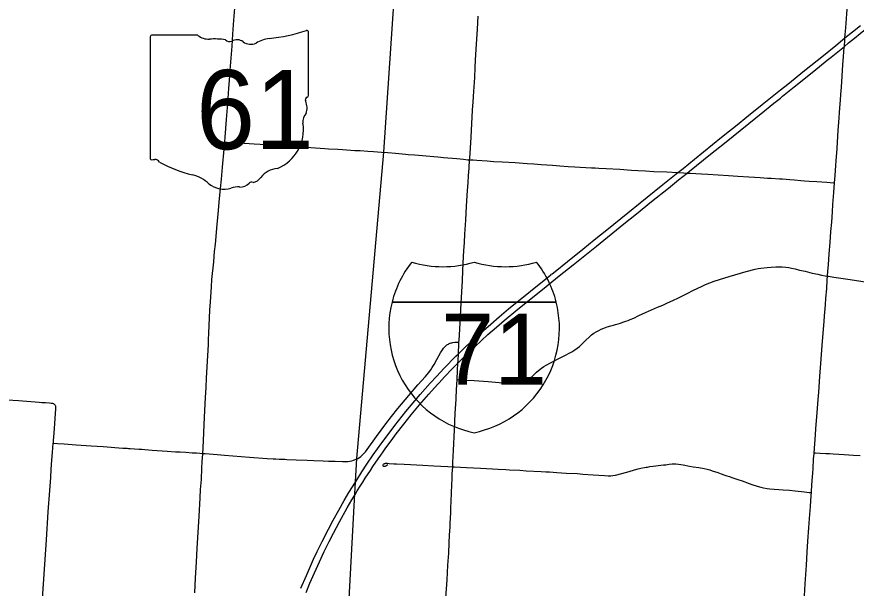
# Model space of a CAD drawing. Extents: x 1815539 to 1947826, y 273303 to 993194.
# Drawn here: x 1874888 to 1889640, y 883973 to 894018 of the extents above; entities that cross this region are included whole.
import ezdxf

# ---------------------------------------------------------------- set-up
doc = ezdxf.new("R2010")
doc.units = 0
for name, color, linetype in [('GM_X_County_Road', 7, 'Continuous'), ('GM_X_Interstate_Route', 7, 'Continuous'), ('GM_X_Interstate_Shield', 7, 'Continuous'), ('GM_X_State_Route', 7, 'Continuous'), ('GM_X_Township', 7, 'Continuous'), ('GM_X_Township_Road', 7, 'Continuous'), ('SC_Shading3', 7, 'Continuous')]:
    doc.layers.add(name, color=color, linetype=linetype)

msp = doc.modelspace()

# ---------------------------------------------------------------- linework, layer by layer
at = {"layer": 'GM_X_County_Road'}
for points in [[(1889363, 892553), (1889369, 892649), (1889379, 892780), (1889393, 892976), (1889407, 893172), (1889419, 893319), (1889431, 893483), (1889432, 893498), (1889441, 893615), (1889443, 893646), (1889456, 893826), (1889474, 894072), (1889499, 894399), (1889514, 894595), (1889515, 894607)], [(1882846, 891505), (1882848, 891532), (1882853, 891621), (1882866, 891801), (1882872, 891900), (1882899, 892375), (1882909, 892522), (1882920, 892702), (1882935, 892948), (1882945, 893128), (1882952, 893259), (1882969, 893538), (1882984, 893800), (1882998, 894029)], [(1889261, 891099), (1889270, 891226), (1889283, 891405), (1889288, 891487), (1889303, 891700), (1889326, 892027), (1889335, 892158), (1889354, 892420), (1889363, 892553)], [(1882659, 888298), (1882661, 888330), (1882672, 888525), (1882684, 888755), (1882696, 888984), (1882707, 889181), (1882718, 889377), (1882727, 889558), (1882739, 889804), (1882745, 889902), (1882754, 890049), (1882763, 890197), (1882778, 890442), (1882794, 890688), (1882811, 890966), (1882819, 891097), (1882828, 891228), (1882836, 891359), (1882846, 891505)], [(1889137, 889460), (1889143, 889544), (1889152, 889656), (1889166, 889852), (1889181, 890048), (1889196, 890244), (1889210, 890408), (1889222, 890588), (1889232, 890719), (1889248, 890931), (1889261, 891099)], [(1888900, 886354), (1888922, 886667), (1888931, 886782), (1888942, 886913), (1888955, 887060), (1888971, 887288), (1888981, 887419), (1889002, 887697), (1889019, 887926), (1889043, 888237), (1889055, 888384), (1889077, 888662), (1889084, 888760), (1889100, 888956), (1889109, 889070), (1889122, 889233), (1889132, 889394), (1889137, 889460)], [(1882656, 888246), (1882659, 888298)], [(1882633, 887798), (1882633, 887803), (1882640, 887930), (1882642, 887973), (1882648, 888094), (1882650, 888123), (1882656, 888246)], [(1882625, 887645), (1882633, 887798)], [(1882607, 887292), (1882608, 887313), (1882616, 887460), (1882625, 887645)], [(1882549, 886108), (1882553, 886182), (1882563, 886395), (1882581, 886755), (1882594, 887051), (1882607, 887292)], [(1875340, 883767), (1875347, 883875), (1875368, 884219), (1875408, 884824), (1875439, 885315), (1875466, 885691), (1875483, 885919), (1875493, 886066), (1875504, 886222), (1875516, 886361), (1875526, 886521)], [(1888852, 885654), (1888854, 885686), (1888867, 885866), (1888876, 885997), (1888881, 886079), (1888892, 886242), (1888899, 886340), (1888900, 886354)], [(1882394, 883327), (1882396, 883347), (1882399, 883397), (1882414, 883594), (1882429, 883806), (1882450, 884118), (1882466, 884380), (1882480, 884592), (1882489, 884773), (1882494, 884904), (1882502, 885051), (1882505, 885117), (1882513, 885297), (1882517, 885379), (1882523, 885510), (1882528, 885641), (1882535, 885805), (1882538, 885887), (1882542, 885985), (1882549, 886108)], [(1888677, 882955), (1888685, 883069), (1888692, 883183), (1888703, 883347), (1888718, 883576), (1888726, 883707), (1888734, 883838), (1888745, 884050), (1888750, 884132), (1888766, 884378), (1888781, 884607), (1888793, 884803), (1888810, 885032), (1888820, 885196), (1888836, 885408), (1888848, 885605), (1888852, 885654)]]:
    msp.add_lwpolyline(points, dxfattribs=at)
at = {"layer": 'GM_X_Interstate_Route'}
for points in [[(1879882, 883972), (1879977, 884199), (1880029, 884319), (1880104, 884483), (1880167, 884617), (1880254, 884793), (1880366, 885012), (1880450, 885172), (1880545, 885344), (1880642, 885515), (1880726, 885656), (1880838, 885838), (1880850, 885856), (1880952, 886018), (1881042, 886155), (1881153, 886317), (1881305, 886531), (1881412, 886676), (1881531, 886833), (1881724, 887078), (1881818, 887192), (1881977, 887379), (1882150, 887576), (1882261, 887697), (1882396, 887840), (1882604, 888050), (1882648, 888094), (1882743, 888189), (1882887, 888323), (1883009, 888433), (1883218, 888617), (1883367, 888746), (1883531, 888882), (1884271, 889481), (1884280, 889495), (1884296, 889501), (1884348, 889542), (1884565, 889717), (1884833, 889933), (1885037, 890098), (1885255, 890272), (1886214, 891044), (1886508, 891280), (1886597, 891352), (1886801, 891518), (1887273, 891899), (1887414, 892012), (1887516, 892095), (1887745, 892281), (1887989, 892474), (1888309, 892731), (1888437, 892834), (1888731, 893071), (1889063, 893338), (1889280, 893514), (1889443, 893646), (1889573, 893751), (1889714, 893864)], [(1889131, 893254), (1889201, 893310), (1889432, 893498), (1889507, 893558), (1889609, 893641), (1889711, 893723), (1889775, 893774), (1889825, 893815)], [(1882941, 888223), (1883168, 888431), (1883316, 888562), (1883453, 888679), (1883694, 888877), (1884129, 889226), (1884422, 889463), (1884665, 889659), (1885074, 889988), (1885559, 890379), (1885777, 890554), (1886045, 890770), (1886339, 891006), (1886518, 891149), (1886670, 891271), (1886710, 891303), (1887081, 891602), (1887324, 891796), (1888026, 892363), (1888128, 892446), (1888192, 892497), (1888307, 892589), (1888345, 892620), (1888549, 892785), (1888893, 893064), (1889131, 893254)], [(1882310, 887585), (1882404, 887688), (1882540, 887830), (1882640, 887930), (1882807, 888097), (1882926, 888210), (1882941, 888223)], [(1879971, 883899), (1880040, 884065), (1880118, 884246), (1880206, 884440), (1880290, 884618), (1880378, 884795), (1880453, 884941), (1880561, 885143), (1880696, 885387), (1880778, 885529), (1880834, 885622), (1880872, 885684), (1880924, 885767), (1880968, 885837), (1881012, 885906), (1881102, 886043), (1881147, 886111), (1881239, 886247), (1881286, 886315), (1881324, 886368), (1881362, 886422), (1881498, 886607), (1881557, 886686), (1881687, 886855), (1881821, 887020), (1881968, 887197), (1882129, 887384), (1882282, 887555), (1882310, 887585)]]:
    msp.add_lwpolyline(points, dxfattribs=at)
at = {"layer": 'GM_X_Interstate_Shield'}
for p, q in [((1881482, 889003), (1884368, 889003)), ((1884368, 889003), (1881482, 889003)), ((1884368, 889003), (1881482, 889003))]:
    msp.add_line(p, q, dxfattribs=at)
for centre, start, end in [((1883300, 888544), 141.669, 165.8066), ((1882377, 891500), 253.0091, 286.9909), ((1883473, 891500), 253.0091, 286.9909), ((1882550, 888544), 14.1934, 38.331), ((1883300, 888544), 165.8066, 258.463), ((1882550, 888544), 281.537, 14.1934)]:
    msp.add_arc(centre, 1875, start, end, dxfattribs=at)
at = {"layer": 'GM_X_State_Route'}
msp.add_lwpolyline([(1878014, 883891), (1878029, 884153), (1878044, 884431), (1878059, 884676), (1878091, 885233), (1878111, 885560), (1878119, 885708), (1878131, 885887), (1878142, 886083), (1878148, 886198), (1878155, 886329), (1878156, 886344), (1878162, 886443), (1878175, 886705), (1878183, 886852), (1878194, 887096), (1878205, 887324), (1878214, 887504), (1878223, 887668), (1878232, 887864), (1878254, 888257), (1878257, 888339), (1878263, 888454), (1878281, 888863), (1878290, 889010), (1878307, 889272), (1878318, 889402), (1878350, 889712), (1878365, 889892), (1878377, 890022), (1878408, 890365), (1878432, 890610), (1878446, 890757), (1878469, 891002), (1878484, 891165), (1878504, 891377), (1878531, 891688), (1878543, 891817), (1878550, 891900), (1878574, 892210), (1878591, 892423), (1878609, 892668), (1878615, 892766), (1878625, 892897), (1878638, 893077), (1878654, 893289), (1878670, 893502), (1878685, 893714), (1878704, 893959), (1878720, 894172)], dxfattribs=at)
at = {"layer": 'GM_X_Township'}
msp.add_lwpolyline([(1880714, 883463), (1880836, 885744), (1880863, 886256), (1881338, 891636), (1881703, 897023), (1881803, 900282), (1881806, 900375), (1881918, 903829), (1881985, 905459), (1882074, 908232), (1882082, 908847), (1882260, 912507), (1887758, 913255), (1888309, 913332)], dxfattribs=at)
at = {"layer": 'GM_X_Township_Road'}
for points in [[(1878543, 891817), (1878585, 891814), (1878666, 891809), (1878797, 891801), (1879059, 891785), (1879272, 891770), (1879403, 891762), (1879534, 891754), (1879730, 891741), (1879910, 891730), (1880058, 891720), (1880303, 891704), (1880368, 891699), (1880532, 891689), (1880614, 891684), (1880826, 891670), (1880925, 891665), (1881055, 891655), (1881154, 891649)], [(1881154, 891649), (1881297, 891639), (1881407, 891632), (1881544, 891621), (1881718, 891605), (1881766, 891600), (1881881, 891590), (1882085, 891574), (1882289, 891556), (1882342, 891549), (1882386, 891544), (1882623, 891524), (1882741, 891513), (1882816, 891506), (1882846, 891505)], [(1882846, 891505), (1882909, 891501), (1882975, 891497), (1883154, 891483), (1883269, 891476), (1883416, 891468), (1883645, 891455), (1883858, 891440), (1883973, 891431), (1884103, 891422), (1884300, 891409), (1884431, 891399), (1884578, 891389), (1884693, 891381), (1884791, 891375), (1884888, 891370), (1884986, 891364), (1885051, 891360), (1885117, 891357), (1885248, 891349), (1885487, 891338), (1885690, 891324), (1885805, 891318), (1885936, 891310), (1886083, 891300), (1886313, 891292), (1886508, 891280), (1886607, 891275), (1886670, 891271), (1886722, 891268), (1886919, 891257), (1887033, 891250), (1887213, 891238), (1887393, 891228), (1887557, 891217), (1887753, 891203), (1887953, 891192), (1888081, 891184), (1888146, 891181), (1888293, 891172), (1888342, 891167), (1888473, 891159), (1888555, 891153), (1888668, 891142), (1888733, 891137), (1888815, 891131), (1888946, 891124), (1889126, 891110), (1889240, 891101), (1889261, 891099)], [(1882625, 887645), (1882633, 887644), (1882698, 887639), (1882796, 887631), (1882927, 887622), (1883172, 887606), (1883368, 887592), (1883462, 887585), (1883565, 887574), (1883647, 887569), (1883695, 887570), (1883744, 887574), (1883776, 887580), (1883792, 887585), (1883807, 887591), (1883822, 887598), (1883836, 887606), (1883850, 887614), (1883877, 887634), (1883901, 887656), (1883972, 887724), (1884020, 887769), (1884057, 887801), (1884109, 887841), (1884150, 887868), (1884192, 887894), (1884279, 887941), (1884438, 888025), (1884540, 888077), (1884583, 888100), (1884640, 888131), (1884696, 888165), (1884737, 888193), (1884776, 888223), (1884824, 888267), (1884882, 888325), (1884953, 888393), (1884990, 888425), (1885029, 888455), (1885071, 888481), (1885114, 888504), (1885158, 888526), (1885203, 888545), (1885265, 888567), (1885328, 888586), (1885377, 888599), (1885408, 888608), (1885454, 888620), (1885499, 888635), (1885537, 888649), (1885590, 888667), (1885632, 888682), (1885670, 888696), (1885730, 888723), (1885819, 888765), (1885938, 888819), (1886044, 888865), (1886149, 888911), (1886239, 888951), (1886313, 888984), (1886432, 889038), (1886506, 889072), (1886550, 889093), (1886682, 889159), (1886770, 889204), (1886931, 889284), (1886991, 889311), (1887067, 889343), (1887144, 889371), (1887237, 889402), (1887410, 889453), (1887709, 889539), (1887867, 889582), (1887915, 889594), (1887964, 889601), (1888078, 889613), (1888143, 889618), (1888225, 889621), (1888291, 889622), (1888340, 889620), (1888405, 889615), (1888454, 889608), (1888502, 889599), (1888566, 889585), (1888646, 889566), (1888741, 889544), (1888869, 889513), (1888964, 889492), (1889028, 889478), (1889095, 889466), (1889137, 889460)], [(1889137, 889460), (1889151, 889457), (1889248, 889441), (1889491, 889404), (1889685, 889375), (1889896, 889342), (1890021, 889324), (1890138, 889306), (1890284, 889284), (1890430, 889264), (1890592, 889238), (1890786, 889208), (1890883, 889197), (1890981, 889190), (1891079, 889184), (1891161, 889183), (1891226, 889184), (1891324, 889189), (1891487, 889197), (1891749, 889210), (1891913, 889220), (1892190, 889241), (1892321, 889253), (1892395, 889260)], [(1880865, 886247), (1880880, 886254), (1880908, 886271), (1880935, 886290), (1880960, 886311), (1880983, 886334), (1881016, 886371), (1881046, 886410), (1881207, 886638), (1881374, 886863), (1881473, 886994), (1881586, 887135), (1881775, 887363), (1881936, 887549), (1882068, 887695), (1882122, 887758), (1882162, 887810), (1882190, 887851), (1882224, 887907), (1882272, 887993), (1882336, 888108), (1882370, 888164), (1882388, 888191), (1882409, 888216), (1882421, 888228), (1882433, 888239), (1882446, 888249), (1882460, 888258), (1882474, 888266), (1882489, 888273), (1882504, 888279), (1882520, 888285), (1882536, 888289), (1882552, 888292), (1882584, 888296), (1882617, 888297), (1882659, 888298)], [(1874626, 887293), (1874920, 887271), (1875280, 887242), (1875330, 887240), (1875346, 887238), (1875395, 887236), (1875461, 887232), (1875489, 887229), (1875510, 887226), (1875517, 887225), (1875526, 887222), (1875533, 887218), (1875540, 887214), (1875546, 887209), (1875552, 887204), (1875557, 887197), (1875562, 887190), (1875565, 887182), (1875567, 887174), (1875568, 887167), (1875569, 887158), (1875568, 887126), (1875538, 886700), (1875529, 886569), (1875526, 886521)], [(1875526, 886521), (1875604, 886516), (1875719, 886509), (1875931, 886494), (1876193, 886478), (1876405, 886463), (1876749, 886437), (1876825, 886433), (1876850, 886431), (1876861, 886430), (1876867, 886430), (1876872, 886429), (1876879, 886429), (1876956, 886424), (1877035, 886419), (1877083, 886416), (1877137, 886412), (1877268, 886402), (1877529, 886384), (1877676, 886373), (1877758, 886368), (1877856, 886363), (1877970, 886355), (1878048, 886351), (1878103, 886347), (1878156, 886344)], [(1888900, 886354), (1888924, 886353), (1889005, 886348), (1889104, 886342), (1889169, 886339), (1889234, 886336), (1889332, 886330), (1889429, 886324), (1889511, 886318), (1889593, 886314), (1889707, 886307)], [(1878156, 886344), (1878197, 886342), (1878409, 886323), (1878539, 886312), (1878980, 886279), (1879290, 886254), (1879394, 886248), (1879442, 886245), (1879496, 886243), (1879540, 886242), (1879583, 886240), (1879599, 886240), (1879632, 886237), (1879795, 886230), (1879992, 886222), (1880106, 886219), (1880270, 886211), (1880368, 886207), (1880429, 886205)], [(1880429, 886205), (1880482, 886204), (1880613, 886199), (1880660, 886199), (1880692, 886199), (1880708, 886200), (1880741, 886205), (1880773, 886212), (1880804, 886222), (1880850, 886240), (1880865, 886247)], [(1881406, 886145), (1881389, 886132), (1881379, 886125), (1881374, 886121), (1881365, 886116), (1881361, 886115), (1881357, 886113), (1881353, 886113), (1881350, 886112), (1881346, 886112), (1881341, 886113), (1881337, 886114), (1881334, 886116), (1881331, 886118), (1881328, 886121), (1881326, 886125), (1881325, 886129), (1881324, 886132), (1881324, 886134), (1881325, 886138), (1881326, 886142), (1881327, 886144), (1881331, 886151), (1881334, 886154), (1881338, 886158), (1881340, 886160), (1881345, 886162), (1881351, 886165), (1881359, 886168), (1881367, 886169), (1881374, 886170), (1881383, 886170), (1881400, 886169), (1881432, 886167), (1881514, 886161), (1881563, 886159), (1881694, 886151), (1882022, 886135), (1882219, 886126), (1882465, 886111), (1882549, 886108)], [(1882549, 886108), (1882579, 886106), (1882792, 886095), (1883038, 886083), (1883251, 886071), (1883349, 886065), (1883480, 886058), (1883546, 886055), (1883726, 886046), (1883841, 886039), (1884103, 886026), (1884185, 886021), (1884250, 886017), (1884381, 886009), (1884544, 885998), (1884740, 885988), (1884838, 885981), (1885019, 885969), (1885215, 885954), (1885281, 885951), (1885330, 885951), (1885362, 885954), (1885411, 885963), (1885522, 885991), (1885649, 886024), (1885744, 886052), (1885807, 886071), (1885854, 886083), (1885918, 886096), (1885950, 886102), (1885970, 886104), (1886014, 886110), (1886074, 886117), (1886121, 886123), (1886162, 886129), (1886208, 886134), (1886255, 886140), (1886292, 886145), (1886354, 886153), (1886403, 886157), (1886436, 886158), (1886469, 886157), (1886518, 886153), (1886599, 886142), (1886712, 886120), (1886776, 886109), (1886873, 886095), (1886906, 886091), (1886938, 886086), (1886970, 886079), (1887018, 886067), (1887065, 886053), (1887110, 886039), (1887208, 886005), (1887265, 885985), (1887315, 885969), (1887367, 885951), (1887414, 885935), (1887457, 885921), (1887491, 885910), (1887561, 885886), (1887638, 885859), (1887761, 885814), (1887807, 885798), (1887900, 885765), (1887963, 885747), (1888011, 885736), (1888075, 885725), (1888124, 885718), (1888354, 885704), (1888468, 885694), (1888566, 885684), (1888729, 885666), (1888811, 885658), (1888852, 885654)]]:
    msp.add_lwpolyline(points, dxfattribs=at)
at = {"layer": 'SC_Shading3'}
for p, q in [((1880013, 892638), (1880013, 893744)), ((1877229, 893655), (1877229, 891542)), ((1878072, 893692), (1877256, 893692)), ((1880013, 892639), (1880013, 892638))]:
    msp.add_line(p, q, dxfattribs=at)
for centre, radius, start, end in [((1879022, 896573), 2953, 275.8445, 288.9065), ((1879982, 893749), 31, 351.8621, 97.738), ((1877261, 893660), 32.3, 98.1301, 188.1301), ((1878266, 893937), 313, 231.6195, 271.1119), ((1878370, 892505), 1123, 80.4867, 94.9883), ((1878625, 893671), 90.3, 219.7921, 297.1024), ((1878757, 893426), 188, 54.4667, 119.1411), ((1878999, 893761), 226, 233.8562, 294.8282), ((1879398, 893046), 594, 97.3462, 120.7689), ((1880006, 892557), 48, 107.944, 210.337), ((1879980, 892634), 33.2, 289.6038, 7.7341), ((1879701, 892418), 288, 340.033, 23.6496), ((1880124, 892176), 210, 136.8065, 186.9296), ((1879187, 892035), 739, 292.3089, 8.9858), ((1877261, 891537), 32.5, 171.9584, 258.3066), ((1877266, 891754), 248, 267.339, 280.6039), ((1877317, 891420), 89.5, 29.7484, 93.2717), ((1878448, 893319), 2132, 240.4129, 257.1985), ((1877812, 890593), 667, 47.1842, 75.836), ((1879498, 890949), 404, 94.4031, 142.5768), ((1878533, 891410), 423, 230.7004, 286.2918), ((1878809, 891251), 226, 268.777, 315.5493), ((1879013, 891047), 63.5, 65.7517, 132.6484), ((1878986, 891337), 239, 282.8732, 323.2771), ((1878778, 890679), 348, 85.6951, 111.2099)]:
    msp.add_arc(centre, radius, start, end, dxfattribs=at)

# ---------------------------------------------------------------- texts
at = {"layer": 'GM_X_Interstate_Shield'}
msp.add_text('71', height=1250, dxfattribs=at).set_placement((1882348, 887550))
at = {"layer": 'SC_Shading3'}
msp.add_text('61', height=1392.2, dxfattribs=at).set_placement((1878039, 891691))

doc.saveas('drawing.dxf')
